// Mitsubishi GX Works2 project: 56.PTO输出（M8349：脉冲输出停止）   PLC: FX3U/FX3UC

PROGRAM MAIN
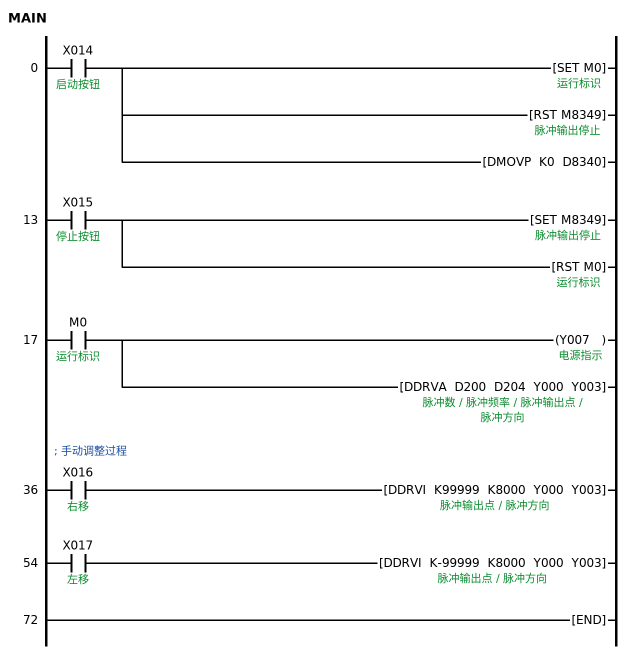
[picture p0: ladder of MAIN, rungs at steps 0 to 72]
0     LD      X014  ; 启动按钮
      SET     M0  ; 运行标识
      RST     M8349  ; 脉冲输出停止
      DMOVP   K0 D8340
        [note] 数据初始化
13    LD      X015  ; 停止按钮
      SET     M8349  ; 脉冲输出停止
      RST     M0  ; 运行标识
17    LD      M0  ; 运行标识
      OUT     Y007  ; 电源指示
      DDRVA   D200 D204 Y000 Y003  ; 脉冲数 / 脉冲频率 / 脉冲输出点 / 脉冲方向
; 手动调整过程
36    LD      X016  ; 右移
      DDRVI   K99999 K8000 Y000 Y003
54    LD      X017  ; 左移
      DDRVI   K-99999 K8000 Y000 Y003
72    END
END_PROGRAM
